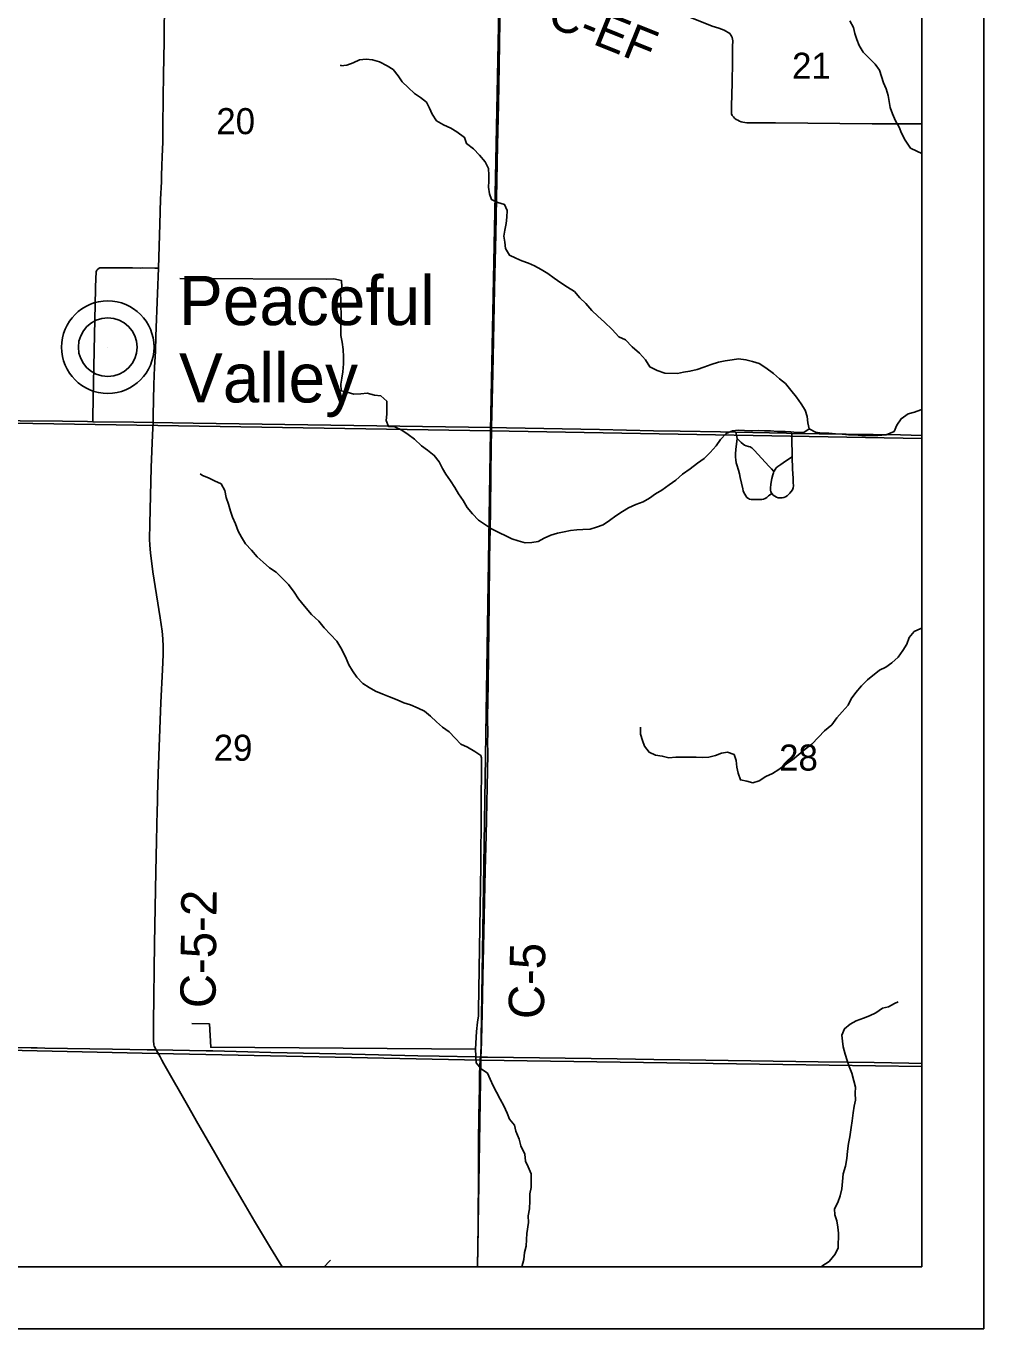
# Model space of a CAD drawing. Extents: x 0 to 42, y 0 to 22.
# Drawn here: x 7.46 to 9, y 14 to 16.093 of the extents above; entities that cross this region are included whole.
import ezdxf

# ---------------------------------------------------------------- set-up
doc = ezdxf.new("R2010")
doc.units = 0
for name, color, linetype in [('Default', 7, 'Continuous'), ('GM_X_County_Road', 7, 'Continuous'), ('GM_X_County_Road_Text', 7, 'Continuous'), ('GM_X_Interchange_Ramps', 7, 'Continuous'), ('GM_X_Minor_River', 7, 'Continuous'), ('GM_X_Section', 7, 'Continuous'), ('GM_X_Section_Text', 7, 'Continuous'), ('GM_X_Township_Road', 7, 'Continuous'), ('GM_X_Unincorporated', 7, 'Continuous'), ('GM_X_Unincorporated_Location', 7, 'Continuous'), ('GM_X_Unincorporated_Text', 7, 'Continuous'), ('SH_Data', 7, 'Continuous')]:
    doc.layers.add(name, color=color, linetype=linetype)

msp = doc.modelspace()

# ---------------------------------------------------------------- linework, layer by layer
at = {"layer": 'Default'}
for points in [[(8.9, 15.4308), (8.9, 16.4352), (8.2267, 16.4466), (8.207, 15.4431)], [(8.9, 14.4214), (8.9, 15.4308), (8.207, 15.4431), (8.1913, 14.4319), (8.6766, 14.425)], [(7.1834, 14.1), (8.1861, 14.1), (8.1913, 14.4319), (7.6712, 14.4424), (7.1882, 14.4532)], [(8.1861, 14.1), (8.9, 14.1), (8.9, 14.4214), (8.6766, 14.425), (8.1913, 14.4319)]]:
    msp.add_lwpolyline(points, close=True, dxfattribs=at)
at = {"layer": 'GM_X_County_Road'}
msp.add_line((7.6695, 14.4487), (7.7497, 14.4468), dxfattribs=at)
for points in [[(7.673, 15.7041), (7.6756, 15.775), (7.6767, 15.8153), (7.6781, 15.8432), (7.6782, 15.8534), (7.6787, 15.8687), (7.679, 15.8839), (7.68, 15.9068), (7.6803, 15.9317), (7.6808, 15.9781), (7.6815, 16.0154), (7.6824, 16.0683), (7.683, 16.1398), (7.6832, 16.1678), (7.6842, 16.1989), (7.6847, 16.2021), (7.6859, 16.2053), (7.6877, 16.2067)], [(8.2084, 15.4481), (8.2093, 15.4919), (8.2105, 15.5354), (8.2115, 15.5883), (8.2134, 15.6721), (8.2152, 15.7591), (8.2183, 15.902), (8.2195, 15.9673), (8.2207, 16.0295), (8.2218, 16.101), (8.223, 16.1632), (8.2236, 16.2028)], [(8.5083, 16.115), (8.5632, 16.0932), (8.574, 16.0897), (8.5824, 16.0866), (8.5914, 16.0813), (8.5944, 16.0769), (8.5952, 16.075), (8.5963, 16.0695), (8.596, 16.0603), (8.5959, 16.0362), (8.5953, 16.002), (8.5941, 15.9646), (8.594, 15.9553), (8.5942, 15.9523), (8.5954, 15.9497), (8.5972, 15.9474), (8.5993, 15.9454), (8.6019, 15.9434), (8.6042, 15.942), (8.6069, 15.9407), (8.6098, 15.9396), (8.6127, 15.9388), (8.6157, 15.9382), (8.6188, 15.9379), (8.6652, 15.9377), (8.8205, 15.9364), (8.8733, 15.9364), (8.9, 15.9362)], [(7.6645, 15.4562), (7.6645, 15.4677), (7.666, 15.5174), (7.667, 15.5454), (7.6682, 15.5702), (7.6688, 15.5951), (7.6714, 15.6634), (7.673, 15.7041)], [(7.6695, 14.4487), (7.6682, 14.4506), (7.6663, 14.4545), (7.6656, 14.4567), (7.6654, 14.4633), (7.6651, 14.4918), (7.6666, 14.6193), (7.6691, 14.7343), (7.6699, 14.7841), (7.6712, 14.8336), (7.6718, 14.8457), (7.6719, 14.8579), (7.672, 14.8735), (7.6726, 14.8922), (7.6772, 15.0067), (7.6796, 15.059), (7.6806, 15.0838), (7.6806, 15.0962), (7.68, 15.1086), (7.6789, 15.1209), (7.6759, 15.1425), (7.6644, 15.2162), (7.6606, 15.247), (7.6594, 15.2594), (7.659, 15.2688), (7.6593, 15.2937), (7.6616, 15.3838), (7.6638, 15.4366), (7.6645, 15.4562)], [(8.191, 14.4369), (8.1915, 14.4405), (8.1918, 14.4429), (8.1919, 14.4452), (8.1926, 14.4638), (8.1934, 14.5074), (8.1948, 14.5664), (8.1957, 14.613), (8.1985, 14.7373), (8.1998, 14.793), (8.2025, 14.9234), (8.2021, 14.945), (8.2025, 14.9543), (8.2022, 14.983), (8.2029, 15.0357), (8.2034, 15.0823), (8.2045, 15.1662), (8.2055, 15.2374), (8.2063, 15.2871), (8.2067, 15.312), (8.2073, 15.3771), (8.2084, 15.4481)], [(7.1857, 14.4561), (7.2357, 14.4554), (7.3321, 14.4538), (7.4004, 14.4526), (7.4687, 14.4518), (7.478, 14.4516), (7.4904, 14.4511), (7.5991, 14.4495), (7.6551, 14.4487), (7.6695, 14.4487)], [(7.7497, 14.4468), (7.7607, 14.4466), (7.8167, 14.4453), (7.854, 14.4443), (7.9845, 14.4413), (8.0901, 14.4389), (8.1243, 14.4382), (8.183, 14.437), (8.191, 14.4369)], [(8.1862, 14.1), (8.187, 14.1615), (8.1871, 14.1926), (8.1874, 14.2299), (8.1877, 14.2766), (8.1878, 14.3014), (8.1883, 14.3417), (8.1894, 14.388), (8.1893, 14.4065), (8.1896, 14.4251), (8.19, 14.4296), (8.1905, 14.4344), (8.191, 14.4369)], [(8.191, 14.4369), (8.202, 14.4366), (8.4102, 14.4338), (8.4693, 14.433), (8.5532, 14.432), (8.7335, 14.4293), (8.7801, 14.4284), (8.8236, 14.4279), (8.8795, 14.4268), (8.9, 14.4265)]]:
    msp.add_lwpolyline(points, dxfattribs=at)
at = {"layer": 'GM_X_Interchange_Ramps'}
msp.add_lwpolyline([(6.2205, 16.2146), (6.2063, 15.4779), (6.1883, 14.4744), (6.182, 14.1), (8.9, 14.1), (8.9, 18.4589)], dxfattribs=at)
at = {"layer": 'GM_X_Minor_River'}
for points in [[(8.9, 15.8887), (8.8922, 15.8925), (8.882, 15.8972), (8.8732, 15.91), (8.8674, 15.9211), (8.8638, 15.931), (8.8579, 15.941), (8.8528, 15.9525), (8.8493, 15.9625), (8.8479, 15.972), (8.8462, 15.9815), (8.843, 15.9922), (8.8387, 16.0022), (8.8355, 16.0125), (8.8319, 16.0224), (8.8249, 16.032), (8.8156, 16.0417), (8.806, 16.0514), (8.7993, 16.0622), (8.7957, 16.0717), (8.7925, 16.0813), (8.7904, 16.0908), (8.7846, 16.1016)], [(8.4236, 15.5891), (8.4131, 15.5942), (8.4023, 15.6058), (8.3901, 15.6175), (8.3796, 15.6272), (8.37, 15.6361), (8.36, 15.6477), (8.3503, 15.6566), (8.3418, 15.6667), (8.3309, 15.6737), (8.3197, 15.6808), (8.3093, 15.6882), (8.2992, 15.696), (8.2883, 15.7023), (8.2775, 15.7082), (8.2677, 15.7122), (8.2575, 15.7162), (8.2478, 15.7202), (8.2373, 15.725), (8.231, 15.7361), (8.2297, 15.746), (8.2284, 15.7555), (8.2297, 15.7654), (8.2322, 15.7763), (8.2332, 15.7865), (8.2334, 15.7972), (8.2294, 15.8067), (8.2189, 15.81), (8.2087, 15.8144), (8.2052, 15.8239), (8.2038, 15.8342), (8.2044, 15.8441), (8.2042, 15.854), (8.2037, 15.8646), (8.1982, 15.8753), (8.189, 15.8858), (8.1793, 15.8962), (8.1685, 15.9044), (8.1649, 15.9144), (8.1526, 15.9233), (8.1429, 15.9292), (8.1312, 15.9344), (8.12, 15.9411), (8.113, 15.9515), (8.109, 15.9614), (8.1039, 15.971), (8.0942, 15.9784), (8.0845, 15.9851), (8.0745, 15.9948), (8.0648, 16.0037), (8.0582, 16.0133), (8.0504, 16.0234), (8.0407, 16.0293), (8.0283, 16.0356), (8.0174, 16.0392), (8.0068, 16.0402), (7.9965, 16.0389), (7.9862, 16.0342), (7.9759, 16.0306), (7.9664, 16.0296), (7.9661, 16.0311)], [(7.9425, 15.6865), (7.7077, 15.6878)], [(8.7192, 15.4464), (8.7104, 15.4401), (8.6994, 15.4404), (8.6897, 15.4411), (8.6807, 15.4419), (8.668, 15.4421), (8.657, 15.4431), (8.6475, 15.4429), (8.6373, 15.4435), (8.627, 15.4432), (8.615, 15.4436), (8.6052, 15.4442), (8.5957, 15.4428), (8.5857, 15.4388), (8.5764, 15.4292), (8.5694, 15.419), (8.5597, 15.4082), (8.5501, 15.3986), (8.5397, 15.3908), (8.5278, 15.3819), (8.5155, 15.3734), (8.5047, 15.3638), (8.4943, 15.356), (8.4824, 15.3475), (8.472, 15.342), (8.4624, 15.3346), (8.4525, 15.3288), (8.4406, 15.3244), (8.4288, 15.3194), (8.4188, 15.3135), (8.4081, 15.3065), (8.3984, 15.2991), (8.3877, 15.2921), (8.3774, 15.2881), (8.3671, 15.2849), (8.3553, 15.2844), (8.3455, 15.2838), (8.3356, 15.2829), (8.3253, 15.2808), (8.3147, 15.2784), (8.304, 15.2756), (8.2933, 15.2705), (8.2834, 15.2653), (8.2731, 15.2633), (8.2625, 15.2631), (8.2512, 15.266), (8.2414, 15.2696), (8.2316, 15.274), (8.2215, 15.2791), (8.2084, 15.2855), (8.1972, 15.2929), (8.1875, 15.2996), (8.1782, 15.3096), (8.1693, 15.32), (8.1627, 15.3308), (8.1553, 15.342), (8.1495, 15.352), (8.1425, 15.3624), (8.1351, 15.3731), (8.1297, 15.3827), (8.1246, 15.3931), (8.1164, 15.4035), (8.1056, 15.4121), (8.0959, 15.4191), (8.0848, 15.4296), (8.0747, 15.437), (8.0646, 15.444), (8.0533, 15.4496), (8.0431, 15.4498), (8.0391, 15.4597), (8.0401, 15.47), (8.0403, 15.4806), (8.0401, 15.4909), (8.0305, 15.499), (8.0206, 15.5004), (8.0086, 15.5036), (7.9987, 15.5023), (7.9873, 15.5018), (7.9764, 15.5051), (7.9666, 15.5071), (7.9661, 15.5178), (7.9681, 15.5276), (7.9695, 15.5378), (7.9705, 15.5504), (7.9707, 15.5621), (7.9702, 15.5735), (7.9685, 15.5853), (7.9665, 15.596), (7.9664, 15.6093), (7.9666, 15.6192), (7.9668, 15.6309), (7.9663, 15.6427), (7.9661, 15.6533), (7.9656, 15.6632), (7.9677, 15.6742), (7.9675, 15.6844), (7.955, 15.687), (7.9425, 15.6865)], [(8.9, 15.477), (8.8986, 15.4766), (8.8883, 15.473), (8.8784, 15.4702), (8.8669, 15.4624), (8.8602, 15.4519), (8.8555, 15.4421), (8.843, 15.4367), (8.8296, 15.4354), (8.82, 15.4354), (8.8128, 15.4357), (8.8035, 15.4356), (8.7921, 15.4366), (8.7823, 15.4364), (8.7723, 15.4376), (8.7615, 15.438), (8.7509, 15.4391), (8.7395, 15.4392), (8.7293, 15.4409), (8.7192, 15.4464), (8.7168, 15.4559), (8.7158, 15.4662), (8.7126, 15.4762), (8.7064, 15.4862), (8.6986, 15.4969), (8.6894, 15.5081), (8.6809, 15.5189), (8.6712, 15.5267), (8.6615, 15.5353), (8.6496, 15.5443), (8.6387, 15.5509), (8.6282, 15.5542), (8.6173, 15.5571), (8.6056, 15.5588), (8.5953, 15.5571), (8.5843, 15.5554), (8.5732, 15.5534), (8.5618, 15.5494), (8.5496, 15.5455), (8.5393, 15.5415), (8.5275, 15.5387), (8.5172, 15.5374), (8.5077, 15.5353), (8.4869, 15.5358), (8.4745, 15.5398), (8.4629, 15.5457), (8.4559, 15.5569), (8.4463, 15.5677), (8.4347, 15.5778), (8.4236, 15.5891)], [(8.1923, 14.9175), (8.1912, 14.9213), (8.1815, 14.9279), (8.1699, 14.9346), (8.1594, 14.9398), (8.1501, 14.9494), (8.1405, 14.9591), (8.1296, 14.9669), (8.12, 14.9755), (8.1103, 14.9844), (8.1006, 14.9926), (8.0905, 14.9974), (8.0781, 15.0025), (8.0675, 15.0062), (8.057, 15.0106), (8.0446, 15.0157), (8.0337, 15.0201), (8.0221, 15.0246), (8.012, 15.0305), (8.0019, 15.0371), (7.9922, 15.0472), (7.9849, 15.0576), (7.979, 15.0672), (7.9739, 15.0798), (7.9663, 15.0944), (7.9597, 15.1048), (7.9497, 15.116), (7.9393, 15.1265), (7.9308, 15.1369), (7.9189, 15.1481), (7.9081, 15.1613), (7.8985, 15.1729), (7.8912, 15.184), (7.8823, 15.1963), (7.8719, 15.2064), (7.8626, 15.2161), (7.8518, 15.2228), (7.8417, 15.2317), (7.8317, 15.2403), (7.8228, 15.2511), (7.8132, 15.2615), (7.8066, 15.2719), (7.8015, 15.2815), (7.7971, 15.2934), (7.7924, 15.3045), (7.7888, 15.314), (7.7857, 15.3251), (7.7821, 15.3358), (7.78, 15.3473), (7.7738, 15.358), (7.7633, 15.3628), (7.7535, 15.3672), (7.7438, 15.3711), (7.74, 15.3739)], [(8.9, 15.1259), (8.8988, 15.1253), (8.8881, 15.1206), (8.8799, 15.1109), (8.8759, 15.1), (8.8697, 15.0899), (8.8622, 15.0794), (8.8518, 15.0701), (8.8422, 15.0635), (8.8319, 15.0583), (8.8126, 15.0428), (8.803, 15.0335), (8.7941, 15.0227), (8.7867, 15.0126), (8.7815, 15.0024), (8.7722, 14.9916), (8.7637, 14.9819), (8.7555, 14.9707), (8.7436, 14.961), (8.7339, 14.9506), (8.7231, 14.9398), (8.7127, 14.9316), (8.7027, 14.9231), (8.6923, 14.9146), (8.6827, 14.908), (8.6704, 14.8991), (8.66, 14.8925), (8.6493, 14.8877), (8.6389, 14.8804), (8.6286, 14.8775), (8.6188, 14.88), (8.6086, 14.8821), (8.6051, 14.8928), (8.6026, 14.9027), (8.6017, 14.9134), (8.5985, 14.9229), (8.5879, 14.9266), (8.5784, 14.9249), (8.5685, 14.9216), (8.5579, 14.9188), (8.5472, 14.9183), (8.5374, 14.9189), (8.5257, 14.9187), (8.5154, 14.9185), (8.5048, 14.9184), (8.4934, 14.9178), (8.4829, 14.9203), (8.4723, 14.9217), (8.4618, 14.9265), (8.4544, 14.9361), (8.4512, 14.9457), (8.448, 14.9556), (8.4478, 14.9651), (8.4478, 14.9666)], [(8.1829, 14.4495), (8.1846, 14.4779), (8.186, 14.4931), (8.1874, 14.5029), (8.1875, 14.512), (8.1915, 14.7443), (8.1923, 14.9175)], [(8.7932, 14.3787), (8.7934, 14.3882), (8.791, 14.3988), (8.7874, 14.4107), (8.7831, 14.4218), (8.7799, 14.4313), (8.7767, 14.4413), (8.7739, 14.4531), (8.7726, 14.4626), (8.7716, 14.4721), (8.7756, 14.4823), (8.7852, 14.4897), (8.7948, 14.4948), (8.8063, 14.4995), (8.8162, 14.5031), (8.8261, 14.5079), (8.8369, 14.5153), (8.8464, 14.5177), (8.8564, 14.5228), (8.8621, 14.5258)], [(8.1829, 14.4495), (7.7571, 14.4527), (7.7552, 14.49), (7.7268, 14.4909)], [(8.2112, 14.3904), (8.2061, 14.4011), (8.2022, 14.4107), (8.1921, 14.4181), (8.1836, 14.4278), (8.1829, 14.4495)], [(8.2572, 14.1), (8.2605, 14.1115), (8.2615, 14.1228), (8.264, 14.133), (8.2646, 14.1437), (8.2652, 14.1531), (8.2678, 14.1709), (8.2676, 14.1819), (8.2694, 14.1929), (8.27, 14.2058), (8.2702, 14.2172), (8.2723, 14.2274), (8.2725, 14.2377), (8.272, 14.2494), (8.2673, 14.2602), (8.263, 14.2698), (8.2621, 14.2808), (8.2555, 14.2942), (8.2527, 14.3049), (8.2476, 14.3175), (8.2452, 14.3275), (8.2374, 14.3371), (8.2335, 14.3467), (8.2284, 14.3582), (8.2225, 14.3693), (8.2163, 14.3804), (8.2112, 14.3904)], [(8.7383, 14.1), (8.7395, 14.101), (8.751, 14.1084), (8.7611, 14.12), (8.7659, 14.1305), (8.7663, 14.1537), (8.765, 14.1636), (8.7633, 14.1739), (8.7605, 14.1834), (8.7599, 14.1929), (8.7654, 14.203), (8.7691, 14.2136), (8.7716, 14.225), (8.7729, 14.2367), (8.7739, 14.2492), (8.7772, 14.2613), (8.7794, 14.2738), (8.7807, 14.2855), (8.7825, 14.298), (8.7842, 14.3086), (8.7868, 14.3234), (8.7882, 14.3344), (8.7896, 14.3472), (8.7913, 14.3578), (8.7934, 14.3677), (8.7932, 14.3787)], [(7.9397, 14.1), (7.9483, 14.109), (7.9499, 14.1105)]]:
    msp.add_lwpolyline(points, dxfattribs=at)
at = {"layer": 'GM_X_Section'}
for points in [[(7.2205, 16.4649), (8.2267, 16.4466), (8.207, 15.4431), (7.2034, 15.459)], [(7.2034, 15.459), (8.207, 15.4431), (8.1913, 14.4319), (7.6712, 14.4424), (7.1882, 14.4532)]]:
    msp.add_lwpolyline(points, close=True, dxfattribs=at)
at = {"layer": 'GM_X_Township_Road'}
msp.add_line((8.6035, 15.4304), (8.6014, 15.4406), dxfattribs=at)
for points in [[(7.5675, 15.4576), (7.5677, 15.4664), (7.5701, 15.572), (7.5722, 15.6709), (7.5726, 15.6899), (7.5729, 15.6955), (7.5732, 15.6984), (7.5742, 15.7012)], [(7.5742, 15.7012), (7.5755, 15.7028), (7.5777, 15.7043), (7.5786, 15.7047), (7.5812, 15.705), (7.5943, 15.705), (7.6013, 15.7048), (7.6066, 15.7049), (7.6312, 15.7047), (7.6436, 15.7045), (7.6478, 15.7047), (7.6675, 15.7042), (7.673, 15.7041)], [(7.3594, 15.46), (7.3949, 15.4595), (7.4508, 15.4589), (7.5191, 15.4585), (7.5593, 15.4577), (7.5675, 15.4576)], [(7.5675, 15.4576), (7.6335, 15.4569), (7.6645, 15.4562)], [(7.6645, 15.4562), (7.6956, 15.4558), (7.7292, 15.4553), (8.2084, 15.4481)], [(8.2084, 15.4481), (8.2328, 15.4477), (8.382, 15.4451), (8.469, 15.4432), (8.5116, 15.4424), (8.5768, 15.4411), (8.6014, 15.4406)], [(8.659, 15.3424), (8.6555, 15.3398), (8.6539, 15.3385), (8.6511, 15.336), (8.6485, 15.3342), (8.6457, 15.3333), (8.6428, 15.3327), (8.6396, 15.3325), (8.6334, 15.3324), (8.6272, 15.3324), (8.6256, 15.3327), (8.6229, 15.3334), (8.6213, 15.3341), (8.619, 15.3361), (8.6171, 15.3385), (8.6155, 15.3411), (8.6142, 15.3439), (8.6131, 15.3468), (8.6122, 15.3498), (8.6101, 15.3589), (8.6084, 15.368), (8.607, 15.3738), (8.6053, 15.3797), (8.6026, 15.3884), (8.6019, 15.3913), (8.6012, 15.3963), (8.6009, 15.4006), (8.6009, 15.406), (8.6014, 15.4129), (8.6035, 15.4304)], [(8.6014, 15.4406), (8.6824, 15.439), (8.6912, 15.4389), (8.8657, 15.4363), (8.9, 15.4357)], [(8.6624, 15.3776), (8.6584, 15.3818), (8.6541, 15.3862), (8.6313, 15.4113), (8.6293, 15.4137), (8.627, 15.4157), (8.626, 15.4164), (8.6243, 15.4172), (8.6213, 15.4179), (8.6178, 15.419), (8.6151, 15.4202), (8.6128, 15.4216), (8.61, 15.424), (8.6035, 15.4304)], [(8.6917, 15.4013), (8.6913, 15.4315), (8.6912, 15.4389)], [(8.659, 15.3424), (8.6613, 15.3398), (8.6638, 15.338), (8.6665, 15.3366), (8.6694, 15.3355), (8.6725, 15.3352), (8.6756, 15.3353), (8.6785, 15.3357), (8.6812, 15.3369), (8.6836, 15.3388), (8.6882, 15.3429), (8.6902, 15.3454), (8.6922, 15.3483), (8.6933, 15.3513), (8.6938, 15.3548), (8.6934, 15.3602), (8.6933, 15.3664), (8.6923, 15.3818), (8.6917, 15.4005), (8.6917, 15.4013)], [(8.6624, 15.3776), (8.6627, 15.3782), (8.6642, 15.3809), (8.6662, 15.3833), (8.6685, 15.3854), (8.6735, 15.3891), (8.6812, 15.3943), (8.6917, 15.4013)], [(8.659, 15.3424), (8.6577, 15.3448), (8.6571, 15.3478), (8.657, 15.3509), (8.6576, 15.3571), (8.6593, 15.3663), (8.6607, 15.3723), (8.6616, 15.3753), (8.6624, 15.3776)], [(7.8718, 14.1), (7.8531, 14.1303), (7.8275, 14.1729), (7.809, 14.2051), (7.7854, 14.2452), (7.7639, 14.2827), (7.7341, 14.3339), (7.7219, 14.3557), (7.682, 14.4258), (7.6787, 14.4318), (7.6759, 14.4371), (7.6695, 14.4487)], [(8.1862, 14.1), (8.187, 14.1615), (8.1871, 14.1926), (8.1874, 14.2299), (8.1877, 14.2766), (8.1878, 14.3014), (8.1883, 14.3417), (8.1894, 14.388), (8.1893, 14.4065), (8.1896, 14.4251), (8.19, 14.4296), (8.1905, 14.4344), (8.191, 14.4369)]]:
    msp.add_lwpolyline(points, dxfattribs=at)
at = {"layer": 'GM_X_Unincorporated'}
for radius in [0.0744, 0.0472]:
    msp.add_circle((7.5917, 15.5774), radius, dxfattribs=at)
at = {"layer": 'GM_X_Unincorporated_Location'}
msp.add_line((7.5917, 15.5774), (7.5917, 15.5774), dxfattribs=at)
at = {"layer": 'SH_Data'}
for p, q in [((9, 21), (9, 14)), ((8.9, 20.9), (8.9, 14.1)), ((2.1, 14.1), (8.9, 14.1)), ((2, 14), (9, 14))]:
    msp.add_line(p, q, dxfattribs=at)

# ---------------------------------------------------------------- texts
at = {"layer": 'GM_X_County_Road_Text'}
for s, rotation, p in [('C-EF', 338.0803, (8.2951, 16.095)), ('C-5-2', 89.4184, (7.7649, 14.5152)), ('C-5', 88.6522, (8.2924, 14.4973))]:
    msp.add_text(s, height=0.05682, rotation=rotation, dxfattribs=at).set_placement(p)
at = {"layer": 'GM_X_Section_Text'}
for s, p in [('21', (8.6916, 16.0086)), ('20', (7.7662, 15.9196)), ('29', (7.762, 14.9129)), ('28', (8.6708, 14.8971))]:
    msp.add_text(s, height=0.04186, rotation=0, dxfattribs=at).set_placement(p)
at = {"layer": 'GM_X_Unincorporated_Text'}
for s, p in [('Peaceful', (7.7062, 15.6128)), ('Valley', (7.7062, 15.4886))]:
    msp.add_text(s, height=0.07898, rotation=0, dxfattribs=at).set_placement(p)

doc.saveas('drawing.dxf')
